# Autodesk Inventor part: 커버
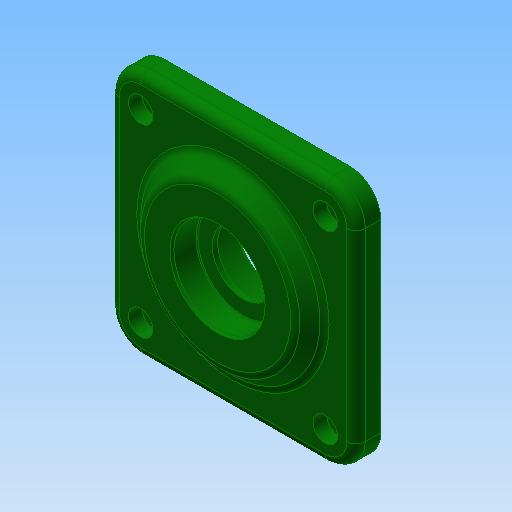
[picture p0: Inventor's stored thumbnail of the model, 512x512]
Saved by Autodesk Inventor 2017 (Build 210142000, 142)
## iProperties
Created: 2016-05
Part Number: 커버
Document SubType Name: Modeling
Designer: mduedu
Density: 2.71 g/cm^3
Material: 알루미늄 6061
Appearance: 진녹색
Author: mduedu
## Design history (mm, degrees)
sketch "스케치1"
  geometry: L1 (-40, -40)-(40, -40); L2 (40, -40)-(40, 40); L3 (40, 40)-(-40, 40); L4 (-40, 40)-(-40, -40); L5 (-40, -40)-(40, 40); L6 (40, -40)-(-40, 40); C1 r 25 at (0, 0); 1 further point
  constraints: 12 end point, 2 midpoint, 2 parallel, 1 centre point, 1 coincident, 1 horizontal, 1 perpendicular
  dimensions: "d30" = 50 diameter of C1; "d33" = 80 distance of L3.end L2.end; "d34" = 80 distance of L2.end L1.end
extrude "돌출1" new body sketch "스케치1" distance "d0" = 8; taper "d1" = 0 deg
fillet "모깎기4" dims "d35" = 10
extrude "돌출2" join sketch "스케치1" distance "d2" = 12; taper "d3" = 0 deg
sketch "스케치2"
  geometry: C1 r 30 at (0, 0); 1 further point
  constraints: 1 centre point, 1 coincident
  dimensions: "d4" = 60 diameter of C1
extrude "돌출3" join sketch "스케치2" distance "d5" = 5; taper "d6" = -45 deg
sketch "스케치3"
  geometry: L1 (30, -40)-(-30, -40) reference; L2 (40, 30)-(40, -30) reference; L3 (-30, 40)-(30, 40) reference; L4 (-40, -30)-(-40, 30) reference; C1 r 30 at (0, 0) reference; A1 r 10 centre (-30, -30) between (-40, -30) and (-30, -40) reference; A2 r 10 centre (30, -30) between (30, -40) and (40, -30) reference; A3 r 10 centre (30, 30) between (40, 30) and (30, 40) reference; A4 r 10 centre (-30, 30) between (-30, 40) and (-40, 30) reference; 4 further points
  constraints: 4 coincident
hole "구멍2" sketch "스케치3" at (-30, 30), (30, 30), (30, -30), (-30, -30) diameter "d36" = 4.5; stored, may be unused: countersink angle "d40" = 90 deg, drill point angle "d42" = 118 deg; dims "d37" = 6, "d38" = 8, "d39" = 4.4, "d41" = 8
fillet "모깎기1" dims "d14" = 3
fillet "모깎기5" dims "d43" = 3
sketch "스케치4"
  geometry: L1 (-23.757, 13)-(23.757, 13) reference; L2 (25, -12)-(-25, -12) reference; L3 (0, -12)-(0, 13); L4 (-20, -12)-(-20, 0); L5 (-20, 0)-(-15, 0); L6 (-15, 0)-(-15, 3); L7 (-15, 3)-(-10, 3); L8 (-10, 3)-(-10, 4.7); L9 (-10, 4.7)-(-15, 4.7); L10 (-15, 4.7)-(-15, 13); 1 further point
  constraints: 16 end point, 6 parallel, 2 midpoint, 2 point on line, 1 perpendicular
  dimensions: "d15" = 40 diameter of L4 L3; "d16" = 30 diameter of L10 L3; "d17" = 8.3 distance of L9.end L10.end; "d18" = 12 distance of L4.start L4.end; "d19" = 3 distance of L5.end L6.end; "d20" = 30 diameter of L6 L3; "d21" = 20 diameter of L8 L3
revolve "회전1" sketch "스케치4" stored, may be unused: angle "d22" = 90 deg
fillet "모깎기2" dims "d23" = 3
fillet "모깎기3" dims "d24" = 0.3
chamfer "모따기1" distance "d25" = 1; stored, may be unused: second distance "d26" = 2, angle "d27" = 45 deg
chamfer "모따기2" distance "d44" = 0.8; stored, may be unused: second distance "d45" = 2, angle "d46" = 30 deg
node "솔리드1"
node "투영된 루프1"
